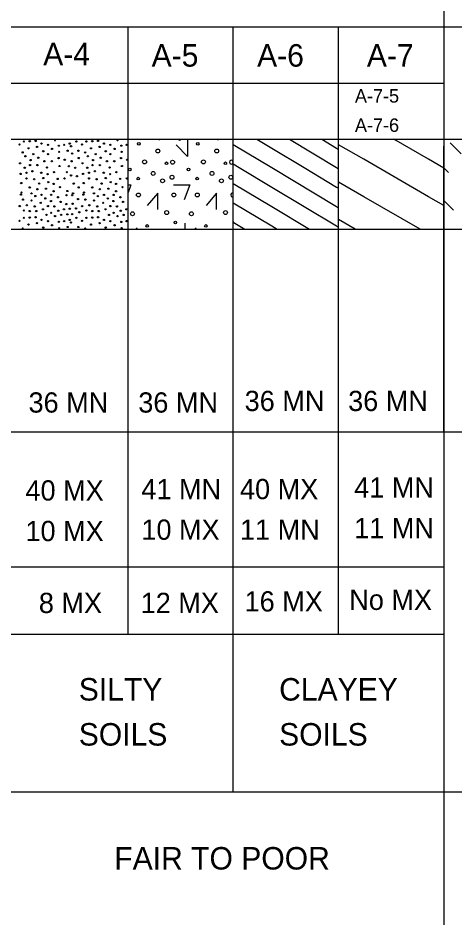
# Model space of a CAD drawing. Extents: x 278710 to 279187, y 171464 to 171625.
# Drawn here: x 279023.58 to 279032.01, y 171537.45 to 171554.93 of the extents above; entities that cross this region are included whole.
import ezdxf

# ---------------------------------------------------------------- set-up
doc = ezdxf.new("R2010")
doc.units = 0
doc.layers.add('Prop Strc Sect_ Misc - User Comment (Tx - small)', color=7, linetype='Continuous')

msp = doc.modelspace()

# ---------------------------------------------------------------- linework, layer by layer
at = {"layer": 'Prop Strc Sect_ Misc - User Comment (Tx - small)'}
for p, q in [((279031.791, 171556.932), (279031.791, 171537.446)), ((279031.791, 171556.932), (279031.791, 171552.486)), ((279005.33, 171554.763), (279043.07, 171554.763)), ((279025.701, 171543.051), (279025.701, 171554.763)), ((279027.731, 171548.529), (279027.731, 171554.763)), ((279029.761, 171543.051), (279029.761, 171554.763)), ((279009.451, 171553.679), (279031.791, 171553.679)), ((279005.33, 171552.594), (279043.07, 171552.594)), ((279027.731, 171552.493), (279028.473, 171552.048)), ((279028.188, 171552.594), (279028.473, 171552.423)), ((279028.813, 171552.594), (279029.723, 171552.048)), ((279029.438, 171552.594), (279029.723, 171552.423)), ((279030.247, 171552.209), (279029.761, 171552.49)), ((279031.497, 171552.209), (279030.831, 171552.594)), ((279031.791, 171546.955), (279031.791, 171552.464)), ((279032.125, 171552.316), (279031.913, 171552.529)), ((279028.473, 171552.423), (279029.097, 171552.048)), ((279029.723, 171552.423), (279029.761, 171552.4)), ((279027.731, 171552.118), (279027.847, 171552.048)), ((279031.497, 171551.487), (279030.247, 171552.209)), ((279031.791, 171552.04), (279031.497, 171552.209)), ((279027.847, 171552.048), (279028.473, 171551.673)), ((279028.473, 171552.048), (279029.723, 171551.298)), ((279029.097, 171552.048), (279029.723, 171551.673)), ((279029.723, 171552.048), (279029.761, 171552.025)), ((279031.883, 171551.952), (279031.791, 171552.043)), ((279027.731, 171551.743), (279028.473, 171551.298)), ((279030.247, 171551.487), (279029.761, 171551.768)), ((279028.473, 171551.673), (279029.723, 171550.923)), ((279029.723, 171551.673), (279029.761, 171551.65)), ((279031.335, 171550.859), (279030.247, 171551.487)), ((279031.791, 171551.318), (279031.497, 171551.487)), ((279031.978, 171551.228), (279031.791, 171551.414)), ((279027.731, 171551.368), (279028.473, 171550.923)), ((279028.473, 171551.298), (279029.204, 171550.859)), ((279029.723, 171551.298), (279029.761, 171551.275)), ((279030.085, 171550.859), (279029.761, 171551.046)), ((279005.33, 171550.859), (279043.07, 171550.859)), ((279027.731, 171550.993), (279027.954, 171550.859)), ((279028.473, 171550.923), (279028.579, 171550.859)), ((279029.723, 171550.923), (279029.761, 171550.9)), ((279027.731, 171540.014), (279027.731, 171548.703)), ((279005.33, 171546.955), (279043.07, 171546.955)), ((279005.33, 171544.352), (279031.791, 171544.352)), ((279005.33, 171543.051), (279031.791, 171543.051)), ((279005.33, 171540.014), (279043.07, 171540.014))]:
    msp.add_line(p, q, dxfattribs=at)
for points in [[(279026.306, 171552.576), (279026.306, 171552.594)], [(279026.851, 171552.576), (279026.851, 171552.264), (279026.629, 171552.485)], [(279027.442, 171552.576), (279027.442, 171552.594)], [(279025.701, 171551.719), (279025.756, 171551.719), (279025.701, 171551.567)], [(279026.579, 171551.719), (279026.892, 171551.719), (279026.784, 171551.425)], [(279027.715, 171551.719), (279027.731, 171551.719)], [(279026.273, 171551.242), (279026.273, 171551.555), (279026.071, 171551.315)], [(279027.408, 171551.242), (279027.408, 171551.555), (279027.207, 171551.315)], [(279025.85, 171550.859), (279025.88, 171550.889)], [(279026.794, 171550.98), (279026.794, 171550.859)], [(279026.986, 171550.859), (279027.016, 171550.889)]]:
    msp.add_lwpolyline(points, dxfattribs=at)
for centre, radius in [((279023.607, 171552.494), 0.0125), ((279023.692, 171552.551), 0.0125), ((279023.782, 171552.42), 0.0125), ((279023.806, 171552.556), 0.0125), ((279023.919, 171552.562), 0.0125), ((279023.947, 171552.448), 0.0125), ((279024.032, 171552.511), 0.0125), ((279024.157, 171552.487), 0.0125), ((279024.367, 171552.471), 0.0125), ((279024.469, 171552.488), 0.0125), ((279024.577, 171552.511), 0.0125), ((279024.602, 171552.46), 0.0125), ((279024.704, 171552.551), 0.0125), ((279024.812, 171552.494), 0.0125), ((279024.897, 171552.551), 0.0125), ((279024.987, 171552.42), 0.0125), ((279025.011, 171552.556), 0.0125), ((279025.124, 171552.562), 0.0125), ((279025.152, 171552.448), 0.0125), ((279025.237, 171552.511), 0.0125), ((279025.362, 171552.487), 0.0125), ((279025.572, 171552.471), 0.0125), ((279025.674, 171552.488), 0.0125), ((279025.91, 171552.506), 0.025), ((279027.046, 171552.506), 0.025), ((279023.669, 171552.341), 0.0125), ((279023.721, 171552.267), 0.0125), ((279023.874, 171552.307), 0.0125), ((279024.066, 171552.363), 0.0125), ((279024.157, 171552.307), 0.0125), ((279024.237, 171552.409), 0.0125), ((279024.373, 171552.352), 0.0125), ((279024.537, 171552.374), 0.0125), ((279024.624, 171552.318), 0.0125), ((279024.744, 171552.374), 0.0125), ((279024.874, 171552.341), 0.0125), ((279024.926, 171552.267), 0.0125), ((279025.079, 171552.307), 0.0125), ((279025.271, 171552.363), 0.0125), ((279025.362, 171552.307), 0.0125), ((279025.442, 171552.409), 0.0125), ((279025.578, 171552.352), 0.0125), ((279026.276, 171552.368), 0.0375), ((279027.412, 171552.368), 0.0375), ((279023.618, 171552.131), 0.0125), ((279023.811, 171552.097), 0.0125), ((279023.822, 171552.193), 0.0125), ((279023.953, 171552.097), 0.0125), ((279023.97, 171552.239), 0.0125), ((279024.089, 171552.171), 0.0125), ((279024.231, 171552.171), 0.0125), ((279024.361, 171552.233), 0.0125), ((279024.379, 171552.079), 0.0125), ((279024.481, 171552.199), 0.0125), ((279024.56, 171552.074), 0.0125), ((279024.613, 171552.171), 0.0125), ((279024.749, 171552.233), 0.0125), ((279024.823, 171552.131), 0.0125), ((279025.016, 171552.097), 0.0125), ((279025.027, 171552.193), 0.0125), ((279025.158, 171552.097), 0.0125), ((279025.175, 171552.239), 0.0125), ((279025.294, 171552.171), 0.0125), ((279025.436, 171552.171), 0.0125), ((279025.566, 171552.233), 0.0125), ((279025.584, 171552.079), 0.0125), ((279025.686, 171552.199), 0.0125), ((279026.021, 171552.158), 0.0375), ((279026.443, 171552.132), 0.025), ((279026.561, 171552.152), 0.0375), ((279027.156, 171552.158), 0.0375), ((279027.579, 171552.132), 0.025), ((279023.629, 171551.926), 0.0125), ((279023.709, 171552.046), 0.0125), ((279023.743, 171551.949), 0.0125), ((279023.856, 171551.977), 0.0125), ((279024.027, 171551.949), 0.0125), ((279024.14, 171552.051), 0.0125), ((279024.151, 171551.921), 0.0125), ((279024.271, 171551.961), 0.0125), ((279024.521, 171551.961), 0.0125), ((279024.602, 171551.898), 0.0125), ((279024.681, 171552.046), 0.0125), ((279024.834, 171551.926), 0.0125), ((279024.914, 171552.046), 0.0125), ((279024.948, 171551.949), 0.0125), ((279025.061, 171551.977), 0.0125), ((279025.232, 171551.949), 0.0125), ((279025.345, 171552.051), 0.0125), ((279025.356, 171551.921), 0.0125), ((279025.476, 171551.961), 0.0125), ((279025.734, 171552.013), 0.025), ((279026.186, 171551.936), 0.0375), ((279026.869, 171552.013), 0.025), ((279027.321, 171551.936), 0.0375), ((279023.641, 171551.751), 0.0125), ((279023.743, 171551.841), 0.0125), ((279023.891, 171551.824), 0.0125), ((279023.987, 171551.739), 0.0125), ((279024.066, 171551.847), 0.0125), ((279024.163, 171551.767), 0.0125), ((279024.265, 171551.734), 0.0125), ((279024.344, 171551.83), 0.0125), ((279024.475, 171551.841), 0.0125), ((279024.653, 171551.739), 0.0125), ((279024.716, 171551.881), 0.0125), ((279024.846, 171551.751), 0.0125), ((279024.948, 171551.841), 0.0125), ((279025.096, 171551.824), 0.0125), ((279025.192, 171551.739), 0.0125), ((279025.271, 171551.847), 0.0125), ((279025.368, 171551.767), 0.0125), ((279025.47, 171551.734), 0.0125), ((279025.549, 171551.83), 0.0125), ((279025.68, 171551.841), 0.0125), ((279025.899, 171551.836), 0.025), ((279026.367, 171551.794), 0.0375), ((279026.549, 171551.862), 0.0375), ((279027.034, 171551.836), 0.025), ((279027.503, 171551.794), 0.0375), ((279027.685, 171551.862), 0.0375), ((279023.647, 171551.569), 0.0125), ((279023.806, 171551.666), 0.0125), ((279023.839, 171551.552), 0.0125), ((279023.953, 171551.631), 0.0125), ((279024.117, 171551.642), 0.0125), ((279024.265, 171551.592), 0.0125), ((279024.39, 171551.671), 0.0125), ((279024.532, 171551.597), 0.0125), ((279024.642, 171551.552), 0.0125), ((279024.749, 171551.666), 0.0125), ((279024.852, 171551.569), 0.0125), ((279025.011, 171551.666), 0.0125), ((279025.044, 171551.552), 0.0125), ((279025.158, 171551.631), 0.0125), ((279025.322, 171551.642), 0.0125), ((279025.47, 171551.592), 0.0125), ((279025.595, 171551.671), 0.0125), ((279025.902, 171551.521), 0.0375), ((279026.584, 171551.521), 0.0375), ((279027.038, 171551.521), 0.0375), ((279023.635, 171551.527), 0.0125), ((279023.675, 171551.431), 0.0125), ((279023.839, 171551.414), 0.0125), ((279023.913, 171551.499), 0.0125), ((279024.016, 171551.369), 0.0125), ((279024.032, 171551.522), 0.0125), ((279024.106, 171551.454), 0.0125), ((279024.214, 171551.402), 0.0125), ((279024.219, 171551.522), 0.0125), ((279024.35, 171551.476), 0.0125), ((279024.401, 171551.386), 0.0125), ((279024.515, 171551.516), 0.0125), ((279024.624, 171551.516), 0.0125), ((279024.738, 171551.442), 0.0125), ((279024.84, 171551.527), 0.0125), ((279024.88, 171551.431), 0.0125), ((279025.044, 171551.414), 0.0125), ((279025.118, 171551.499), 0.0125), ((279025.221, 171551.369), 0.0125), ((279025.237, 171551.522), 0.0125), ((279025.311, 171551.454), 0.0125), ((279025.419, 171551.402), 0.0125), ((279025.424, 171551.522), 0.0125), ((279025.555, 171551.476), 0.0125), ((279025.606, 171551.386), 0.0125), ((279023.612, 171551.306), 0.0125), ((279023.692, 171551.221), 0.0125), ((279023.749, 171551.323), 0.0125), ((279023.806, 171551.21), 0.0125), ((279023.902, 171551.301), 0.0125), ((279023.931, 171551.21), 0.0125), ((279024.061, 171551.244), 0.0125), ((279024.157, 171551.306), 0.0125), ((279024.282, 171551.301), 0.0125), ((279024.356, 171551.216), 0.0125), ((279024.464, 171551.244), 0.0125), ((279024.509, 171551.346), 0.0125), ((279024.577, 171551.255), 0.0125), ((279024.631, 171551.352), 0.0125), ((279024.698, 171551.261), 0.0125), ((279024.817, 171551.306), 0.0125), ((279024.897, 171551.221), 0.0125), ((279024.954, 171551.323), 0.0125), ((279025.011, 171551.21), 0.0125), ((279025.107, 171551.301), 0.0125), ((279025.136, 171551.21), 0.0125), ((279025.266, 171551.244), 0.0125), ((279025.362, 171551.306), 0.0125), ((279025.487, 171551.301), 0.0125), ((279025.561, 171551.216), 0.0125), ((279025.669, 171551.244), 0.0125), ((279026.446, 171551.181), 0.0375), ((279027.582, 171551.181), 0.0375), ((279023.607, 171551.022), 0.0125), ((279023.692, 171551.079), 0.0125), ((279023.806, 171551.085), 0.0125), ((279023.919, 171551.091), 0.0125), ((279024.032, 171551.039), 0.0125), ((279024.129, 171551.136), 0.0125), ((279024.219, 171551.176), 0.0125), ((279024.293, 171551.113), 0.0125), ((279024.412, 171551.136), 0.0125), ((279024.532, 171551.147), 0.0125), ((279024.577, 171551.039), 0.0125), ((279024.624, 171551.153), 0.0125), ((279024.704, 171551.079), 0.0125), ((279024.761, 171551.187), 0.0125), ((279024.812, 171551.022), 0.0125), ((279024.897, 171551.079), 0.0125), ((279025.011, 171551.085), 0.0125), ((279025.124, 171551.091), 0.0125), ((279025.237, 171551.039), 0.0125), ((279025.334, 171551.136), 0.0125), ((279025.424, 171551.176), 0.0125), ((279025.498, 171551.113), 0.0125), ((279025.617, 171551.136), 0.0125), ((279025.788, 171551.158), 0.0375), ((279026.924, 171551.158), 0.0375), ((279023.782, 171550.949), 0.0125), ((279023.947, 171550.977), 0.0125), ((279024.066, 171550.892), 0.0125), ((279024.157, 171551.016), 0.0125), ((279024.237, 171550.937), 0.0125), ((279024.367, 171551), 0.0125), ((279024.373, 171550.881), 0.0125), ((279024.469, 171551.017), 0.0125), ((279024.537, 171550.903), 0.0125), ((279024.602, 171550.989), 0.0125), ((279024.744, 171550.903), 0.0125), ((279024.987, 171550.949), 0.0125), ((279025.152, 171550.977), 0.0125), ((279025.271, 171550.892), 0.0125), ((279025.362, 171551.016), 0.0125), ((279025.442, 171550.937), 0.0125), ((279025.572, 171551), 0.0125), ((279025.578, 171550.881), 0.0125), ((279025.674, 171551.017), 0.0125), ((279026.069, 171550.923), 0.025), ((279026.614, 171550.991), 0.025), ((279027.204, 171550.923), 0.025)]:
    msp.add_circle(centre, radius, dxfattribs=at)
for centre, radius, start, end in [((279024.293, 171552.584), 0.0125, 128.4735, 51.5265), ((279025.498, 171552.584), 0.0125, 128.4735, 51.5265), ((279026.697, 171552.617), 0.0375, 217.8115, 322.1885), ((279027.696, 171552.152), 0.0375, 22.8613, 337.1387), ((279027.719, 171551.521), 0.0375, 72.255, 287.745), ((279023.669, 171550.869), 0.0125, 305.1764, 234.8236), ((279024.624, 171550.847), 0.0125, 79.3017, 100.6983), ((279024.874, 171550.869), 0.0125, 305.1764, 234.8236), ((279027.75, 171550.991), 0.025, 140.1592, 219.8408)]:
    msp.add_arc(centre, radius, start, end, dxfattribs=at)

# ---------------------------------------------------------------- texts
for s, height, p in [('A-4', 0.4338, (279024.065, 171554.021)), ('A-5', 0.4338, (279026.156, 171553.995)), ('A-6', 0.4338, (279028.191, 171553.995)), ('A-7', 0.4338, (279030.308, 171553.995)), ('A-7-5', 0.2603, (279030.078, 171553.301)), ('A-7-6', 0.2603, (279030.078, 171552.737)), ('36 MN', 0.3904, (279023.782, 171547.324)), ('36 MN', 0.3904, (279025.899, 171547.324)), ('36 MN', 0.3904, (279027.951, 171547.354)), ('36 MN', 0.3904, (279029.947, 171547.354)), ('40 MX', 0.3904, (279023.723, 171545.628)), ('41 MN', 0.3904, (279025.959, 171545.654)), ('40 MX', 0.3904, (279027.861, 171545.654)), ('41 MN', 0.3904, (279030.064, 171545.684)), ('10 MX', 0.3904, (279025.959, 171544.872)), ('11 MN', 0.3904, (279027.861, 171544.872)), ('11 MN', 0.3904, (279030.064, 171544.902)), ('10 MX', 0.3904, (279023.723, 171544.846)), ('16 MX', 0.3904, (279027.95, 171543.489)), ('No MX', 0.3904, (279029.969, 171543.519)), ('8 MX', 0.3904, (279023.981, 171543.459)), ('12 MX', 0.3904, (279025.946, 171543.459)), ('SILTY', 0.4338, (279024.751, 171541.771)), ('CLAYEY', 0.4338, (279028.616, 171541.771)), ('SOILS', 0.4338, (279024.751, 171540.903)), ('SOILS', 0.4338, (279028.616, 171540.903)), ('FAIR TO POOR', 0.43381, (279025.436, 171538.513))]:
    msp.add_text(s, height=height, dxfattribs=at).set_placement(p)

doc.saveas('drawing.dxf')
